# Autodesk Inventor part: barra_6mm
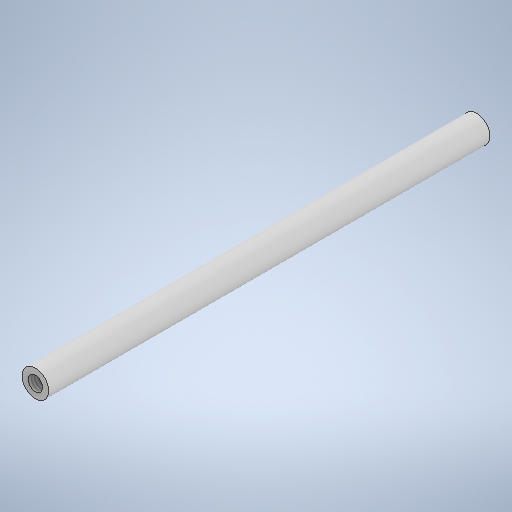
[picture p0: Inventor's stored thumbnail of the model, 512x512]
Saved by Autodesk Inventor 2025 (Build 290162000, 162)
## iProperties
Created: 2025-12
Part Number: barra_6mm
Material: Generico
Document SubType Name: Modeling
Designer: Ryzen5700u
Density: 1 g/cm^3
Appearance: Default
Author: Ryzen5700u
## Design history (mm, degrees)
sketch "Schizzo1"
  geometry: C1 r 3 at (0, 0); 1 further point
  constraints: 1 centre point, 1 coincident
  dimensions: "d0" = 6 diameter of C1
extrude "Estrusione1" new body sketch "Schizzo1" stored distance "d1" = 100; taper "d2" = 0 deg
sketch "Schizzo2"
  geometry: C1 r 3 at (0, 0) reference; 2 further points
  constraints: 1 coincident
hole "Foro1" sketch "Schizzo2" at (0, 0) diameter "d3" = 3.242; stored, may be unused: countersink angle "d7" = 82 deg, drill point angle "d9" = 118 deg; dims "d4" = 8, "d5" = 3.023, "d6" = 2, "d8" = 11.8
sketch "Schizzo3"
  geometry: C1 r 3 at (0, 0) reference; 2 further points
  constraints: 1 coincident
hole "Foro2" sketch "Schizzo3" at (0, 0) diameter "d10" = 3.242; stored, may be unused: countersink angle "d14" = 90 deg, drill point angle "d16" = 118 deg; dims "d11" = 8, "d12" = 4, "d13" = 2, "d15" = 11.8
node "Solido1"
